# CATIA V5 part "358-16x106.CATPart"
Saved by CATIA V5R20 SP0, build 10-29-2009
Part number: 358-16X106
Definition: NONE
Nomenclature: 358-16X106
Source: Unknown
Description: 358-16X106
Bounding box of the stored display mesh (mm): x -15 to 91, y -13 to 13, z -13 to 13
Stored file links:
  C:\Users\Utente\Desktop\IO LAVORO\3D X SITO CF\X SITO\PLASTICA\358\358-16x106.CATPart
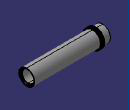
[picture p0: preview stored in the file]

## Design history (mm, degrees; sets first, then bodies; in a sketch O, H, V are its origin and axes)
Body1 "358-16X106" (main body)
  Solid1: solid without history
